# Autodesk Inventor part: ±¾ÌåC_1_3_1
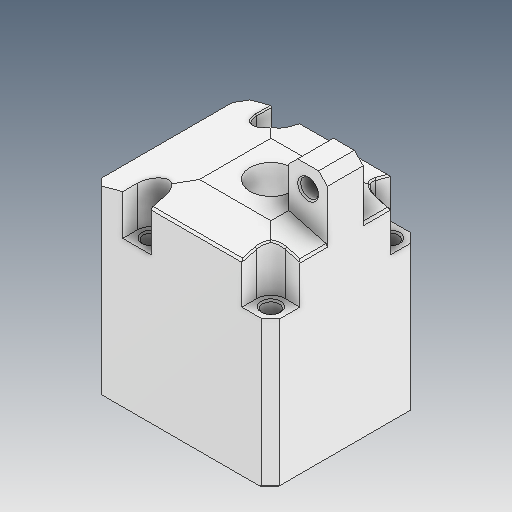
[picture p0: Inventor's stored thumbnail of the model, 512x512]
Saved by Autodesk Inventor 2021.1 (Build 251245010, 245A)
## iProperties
Created: 2021-05
Part Number: ±¾ÌåC_1_3_1
Material: Ogólny
Document SubType Name: Modeling
Designer: user
Density: 1 g/cm^3
Appearance: Domyślna
Author: user
Revision Number: ÈÎºÎ
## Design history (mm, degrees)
feature "ÊäÈë1"
feature "ÊäÈë2"
node "Bryła1"
node "Bryła2"
